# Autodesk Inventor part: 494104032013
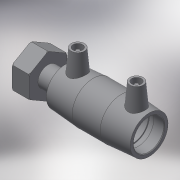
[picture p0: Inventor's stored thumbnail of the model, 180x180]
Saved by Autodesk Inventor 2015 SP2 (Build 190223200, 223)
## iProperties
Created: 2017-06
Part Number: 494104032013
Material: Generic
Description: PLASSON FEMALE FREE NUT TRANSITION COUPLER 32-1.1/4"
Document SubType Name: Modeling
Designer: KIM
Mass: 55.0731 g
Surface Area: 148.067 cm^2
Volume: 55.0731 cm^3
Density: 1 g/cm^3
Appearance: Default
Author: KIM
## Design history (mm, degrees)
derived "494104.ipt"
feature "Solid1::494104.ipt"
tag "TaggingFeature1"
body "Solid1"
other parameters: "d0" = 88, "d1" = 32, "d2" = 44, "d3" = 42, "d4" = 29.33333, "d5" = 39.6, "d6" = 30.4, "d7" = 32, "d8" = 168 deg, "d10" = 16.8, "d11" = 5.6, "d29" = 42, "d30" = 14, "d31" = 30.8, "d34" = 5 deg, "d41" = 4, "d42" = 14, "d43" = 0, "d48" = 3, "d49" = 0, "d55" = 36, "d57" = 23, "d80" = 0.64, "d83" = 18, "d84" = 11.88, "d85" = 1.188, "d86" = 31.1616, "d87" = 38.952, "d88" = 58.428, "d89" = 44, "d90" = 1.16856, "d94" = 0, "d95" = 1.188, "d96" = 27.2664, "d_" = 32, "L_" = 124, "L_1" = 42, "D_1" = 44, "A_" = 42, "d_2" = 12, "L_2" = 36, "D_" = 23, "G_" = 38.952
